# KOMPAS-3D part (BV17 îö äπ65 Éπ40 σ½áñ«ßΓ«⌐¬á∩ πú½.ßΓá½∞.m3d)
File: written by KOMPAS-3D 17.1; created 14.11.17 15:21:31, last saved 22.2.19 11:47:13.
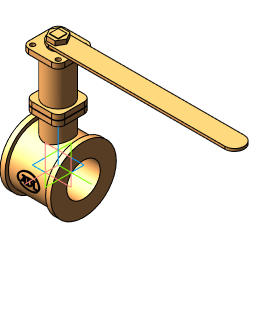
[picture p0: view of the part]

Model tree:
1. Операция без истории:1  (labels: Сталь 20  ГОСТ 1050-2013)

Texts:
  Линейный размер с обрывом
  Толщина листового тела
  Глубина освобождения сгиба
  Ширина освобождения сгиба
  BV17 МФ Ду15 Ру40 хладостойкая угл.сталь
  BV17 МФ Ду20 Ру40 хладостойкая угл.сталь
  BV17 МФ Ду25 Ру40 хладостойкая угл.сталь
  BV17 МФ Ду32 Ру40 хладостойкая угл.сталь
  BV17 МФ Ду40 Ру40 хладостойкая угл.сталь
  BV17 МФ Ду50 Ру40 хладостойкая угл.сталь
  BV17 МФ Ду65 Ру40 хладостойкая угл.сталь
  BV17 МФ Ду80 Ру40 хладостойкая угл.сталь
  BV17 МФ Ду100 Ру40 хладостойкая угл.сталь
